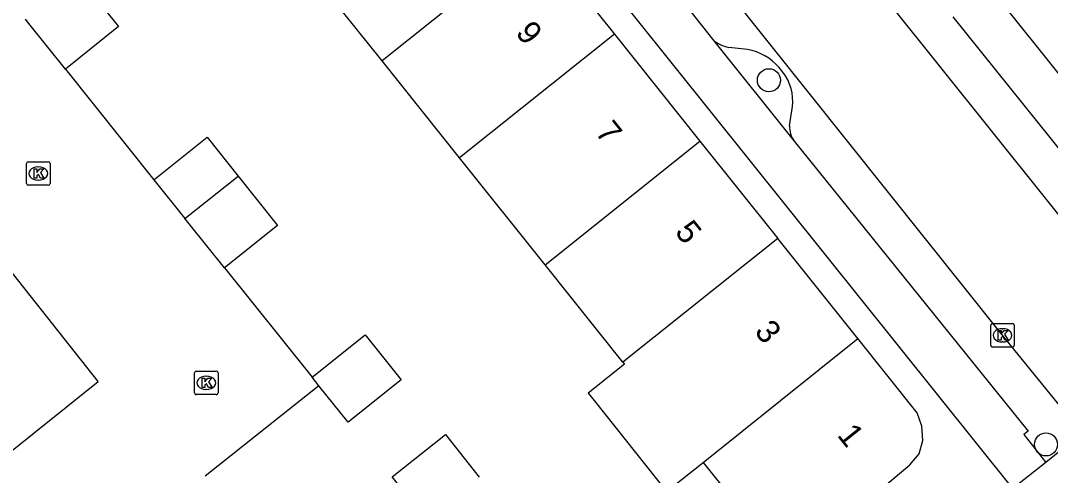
# Model space of a CAD drawing. Extents: x 161771 to 163125, y 382479 to 383177.
# Drawn here: x 162091.27 to 162135.05, y 382896.99 to 382916.33 of the extents above; entities that cross this region are included whole.
import ezdxf

# ---------------------------------------------------------------- set-up
doc = ezdxf.new("R2010")
doc.units = 0
for name, color, linetype in [('IMGEO_Boom', 7, 'Continuous'), ('IMGEO_Kolk', 7, 'Continuous'), ('IMGEO_Pand', 7, 'Continuous'), ('IMGEO_Pand_nummerreeks', 7, 'Continuous'), ('IMGEO_Parkeervlak_open', 7, 'Continuous'), ('IMGEO_Rijbaan_lokaal_open', 7, 'Continuous'), ('IMGEO_Voetpad_open', 7, 'Continuous')]:
    doc.layers.add(name, color=color, linetype=linetype)

msp = doc.modelspace()

# ---------------------------------------------------------------- linework, layer by layer
at = {"layer": 'IMGEO_Boom'}
for centre in [(162123.086, 382913.794), (162134.866, 382898.309)]:
    msp.add_circle(centre, 0.489, dxfattribs=at)
at = {"layer": 'IMGEO_Kolk'}
for p, q in [((162091.519, 382909.401), (162091.519, 382910.253)), ((162091.594, 382910.327), (162092.446, 382910.327)), ((162092.007, 382910.107), (162092.032, 382910.107)), ((162092.52, 382910.253), (162092.52, 382909.401)), ((162092.03, 382909.547), (162092.005, 382909.547)), ((162092.446, 382909.327), (162091.594, 382909.327)), ((162132.516, 382902.522), (162132.516, 382903.374)), ((162132.591, 382903.448), (162133.443, 382903.448)), ((162133.517, 382903.374), (162133.517, 382902.522)), ((162133.004, 382903.228), (162133.029, 382903.228)), ((162133.027, 382902.668), (162133.002, 382902.668)), ((162133.443, 382902.448), (162132.591, 382902.448)), ((162098.663, 382900.5), (162098.663, 382901.352)), ((162098.738, 382901.426), (162099.59, 382901.426)), ((162099.151, 382901.206), (162099.176, 382901.206)), ((162099.664, 382901.352), (162099.664, 382900.5)), ((162099.59, 382900.426), (162098.738, 382900.426)), ((162099.174, 382900.646), (162099.149, 382900.646))]:
    msp.add_line(p, q, dxfattribs=at)
for points in [[(162091.519, 382909.401), (162091.519, 382910.253)], [(162091.594, 382910.327), (162092.446, 382910.327)], [(162091.84, 382910.027), (162091.963, 382910.027), (162091.963, 382909.876), (162092.093, 382910.027), (162092.257, 382910.027), (162092.111, 382909.876), (162092.264, 382909.627), (162092.112, 382909.627), (162092.027, 382909.791), (162091.963, 382909.724), (162091.963, 382909.627), (162091.84, 382909.627), (162091.84, 382910.027)], [(162092.52, 382910.253), (162092.52, 382909.401)], [(162092.446, 382909.327), (162091.594, 382909.327)], [(162132.516, 382902.522), (162132.516, 382903.374)], [(162132.591, 382903.448), (162133.443, 382903.448)], [(162133.517, 382903.374), (162133.517, 382902.522)], [(162132.837, 382903.148), (162132.96, 382903.148), (162132.96, 382902.997), (162133.09, 382903.148), (162133.254, 382903.148), (162133.108, 382902.997), (162133.261, 382902.748), (162133.109, 382902.748), (162133.024, 382902.912), (162132.96, 382902.845), (162132.96, 382902.748), (162132.837, 382902.748), (162132.837, 382903.148)], [(162133.443, 382902.448), (162132.591, 382902.448)], [(162098.663, 382900.5), (162098.663, 382901.352)], [(162098.738, 382901.426), (162099.59, 382901.426)], [(162099.664, 382901.352), (162099.664, 382900.5)], [(162098.984, 382901.126), (162099.107, 382901.126), (162099.107, 382900.975), (162099.237, 382901.126), (162099.401, 382901.126), (162099.255, 382900.975), (162099.408, 382900.726), (162099.256, 382900.726), (162099.171, 382900.89), (162099.107, 382900.823), (162099.107, 382900.726), (162098.984, 382900.726), (162098.984, 382901.126)], [(162099.59, 382900.426), (162098.738, 382900.426)]]:
    msp.add_lwpolyline(points, dxfattribs=at)
for centre, start, end in [((162091.596, 382910.251), 91.552, 178.448), ((162091.596, 382910.251), 91.552, 178.448), ((162092.444, 382910.251), 1.552, 88.448), ((162092.444, 382910.251), 1.552, 88.448), ((162091.596, 382909.403), 181.552, 268.448), ((162091.596, 382909.403), 181.552, 268.448), ((162092.444, 382909.403), 271.552, 358.448), ((162092.444, 382909.403), 271.552, 358.448), ((162132.593, 382903.372), 91.552, 178.448), ((162132.593, 382903.372), 91.552, 178.448), ((162133.441, 382903.372), 1.552, 88.448), ((162133.441, 382903.372), 1.552, 88.448), ((162132.593, 382902.524), 181.552, 268.448), ((162132.593, 382902.524), 181.552, 268.448), ((162133.441, 382902.524), 271.552, 358.448), ((162133.441, 382902.524), 271.552, 358.448), ((162098.74, 382901.35), 91.552, 178.448), ((162098.74, 382901.35), 91.552, 178.448), ((162099.588, 382901.35), 1.552, 88.448), ((162099.588, 382901.35), 1.552, 88.448), ((162098.74, 382900.502), 181.552, 268.448), ((162098.74, 382900.502), 181.552, 268.448), ((162099.588, 382900.502), 271.552, 358.448), ((162099.588, 382900.502), 271.552, 358.448)]:
    msp.add_arc(centre, 0.0765, start, end, dxfattribs=at)
for centre, major_axis, ratio, start_param, end_param in [((162092.006, 382909.827), (-0.387, 0.002), 0.722429, 4.712389, 7.853982), ((162092.031, 382909.827), (-0.39, 0.002), 0.717154, 1.570796, 4.712389), ((162133.003, 382902.948), (-0.387, 0.002), 0.722429, 4.712389, 7.853982), ((162133.028, 382902.948), (-0.39, 0.002), 0.717154, 1.570796, 4.712389), ((162099.15, 382900.926), (-0.387, 0.002), 0.722429, 4.712389, 7.853982), ((162099.175, 382900.926), (-0.39, 0.002), 0.717154, 1.570796, 4.712389)]:
    msp.add_ellipse(centre, major_axis=major_axis, ratio=ratio, start_param=start_param, end_param=end_param, dxfattribs=at)
at = {"layer": 'IMGEO_Pand'}
for points in [[(162113.219, 382919.877), (162106.639, 382914.616)], [(162113.219, 382919.877), (162116.514, 382915.755)], [(162106.639, 382914.616), (162103.332, 382918.753)], [(162093.738, 382918.191), (162095.434, 382916.072), (162093.178, 382914.267)], [(162093.178, 382914.267), (162091.679, 382916.141), (162091.482, 382916.387)], [(162116.514, 382915.755), (162109.935, 382910.493)], [(162116.514, 382915.755), (162120.154, 382911.203)], [(162109.935, 382910.493), (162106.639, 382914.616)], [(162096.938, 382909.564), (162099.195, 382911.37), (162100.516, 382909.72)], [(162113.574, 382905.941), (162120.154, 382911.203)], [(162120.154, 382911.203), (162123.461, 382907.069)], [(162113.574, 382905.941), (162109.935, 382910.493)], [(162096.938, 382909.564), (162098.257, 382907.915)], [(162098.257, 382907.915), (162100.516, 382909.72)], [(162100.516, 382909.72), (162102.194, 382907.623), (162099.938, 382905.818)], [(162099.938, 382905.818), (162098.437, 382907.69), (162098.257, 382907.915)], [(162123.461, 382907.069), (162116.88, 382901.806)], [(162126.866, 382902.81), (162123.461, 382907.069)], [(162116.88, 382901.806), (162113.574, 382905.941)], [(162103.661, 382901.163), (162105.918, 382902.969), (162107.449, 382901.057), (162105.193, 382899.252), (162103.952, 382900.799)], [(162120.285, 382897.547), (162126.866, 382902.81)], [(162120.285, 382897.547), (162125.22, 382891.373), (162127.733, 382893.39), (162126.326, 382895.13), (162129.082, 382897.445), (162129.472, 382897.905), (162129.636, 382898.483), (162129.594, 382899.083), (162129.39, 382899.654), (162126.866, 382902.81)], [(162116.88, 382901.806), (162116.944, 382901.726), (162115.398, 382900.494), (162115.649, 382900.178), (162118.733, 382896.306), (162120.285, 382897.547)], [(162103.952, 382900.799), (162103.661, 382901.163)], [(162108.514, 382895.115), (162107.07, 382896.928), (162109.328, 382898.727), (162110.769, 382896.919)]]:
    msp.add_lwpolyline(points, dxfattribs=at)
at = {"layer": 'IMGEO_Parkeervlak_open'}
for points in [[(162122.176, 382915.105), (162121.383, 382915.189)], [(162123.68, 382914.138), (162123.52, 382914.329)], [(162123.963, 382911.852), (162124.086, 382912.67)]]:
    msp.add_lwpolyline(points, dxfattribs=at)
for centre, radius, start, end in [((162121.587, 382916.449), 1.277, 225.3471, 260.7976), ((162121.726, 382912.773), 2.375, 40.9257, 79.0717), ((162122.072, 382912.903), 2.027, 353.3934, 37.526), ((162125.025, 382911.823), 1.063, 178.4264, 215.9516)]:
    msp.add_arc(centre, radius, start, end, dxfattribs=at)
at = {"layer": 'IMGEO_Rijbaan_lokaal_open'}
for points in [[(162122.694, 382923.973), (162123.703, 382922.674), (162137.054, 382905.998), (162139.34, 382903.102), (162140.307, 382901.917)], [(162136.406, 382898.79), (162133.002, 382902.97), (162119.914, 382919.373), (162118.699, 382920.849)], [(162080.804, 382889.961), (162094.568, 382900.987), (162085.405, 382912.559), (162089.106, 382915.436)], [(162093.178, 382914.267), (162096.938, 382909.564)], [(162099.938, 382905.818), (162103.661, 382901.163)], [(162103.952, 382900.799), (162099.119, 382896.958)]]:
    msp.add_lwpolyline(points, dxfattribs=at)
at = {"layer": 'IMGEO_Voetpad_open'}
for points in [[(162133.454, 382896.443), (162070.869, 382974.514)], [(162096.877, 382962.151), (162143.255, 382904.278)], [(162117.481, 382919.612), (162120.69, 382915.541)], [(162141.717, 382903.048), (162130.917, 382916.483)], [(162120.69, 382915.541), (162124.165, 382911.199)], [(162124.165, 382911.199), (162134.109, 382898.871), (162133.924, 382898.728), (162134.86, 382897.546)], [(162136.406, 382898.79), (162134.86, 382897.546)], [(162134.86, 382897.546), (162133.454, 382896.443)]]:
    msp.add_lwpolyline(points, dxfattribs=at)

# ---------------------------------------------------------------- texts
at = {"layer": 'IMGEO_Pand_nummerreeks'}
for s, rotation, p in [('9', 308.6478, (162112.281, 382915.797)), ('7', 308.6478, (162115.667, 382911.563)), ('5', 308.6478, (162119.053, 382907.329)), ('3', 308.6458, (162122.438, 382903.094)), ('1', 308.6458, (162125.957, 382898.695))]:
    msp.add_text(s, height=1, rotation=rotation, dxfattribs=at).set_placement(p)

doc.saveas('drawing.dxf')
